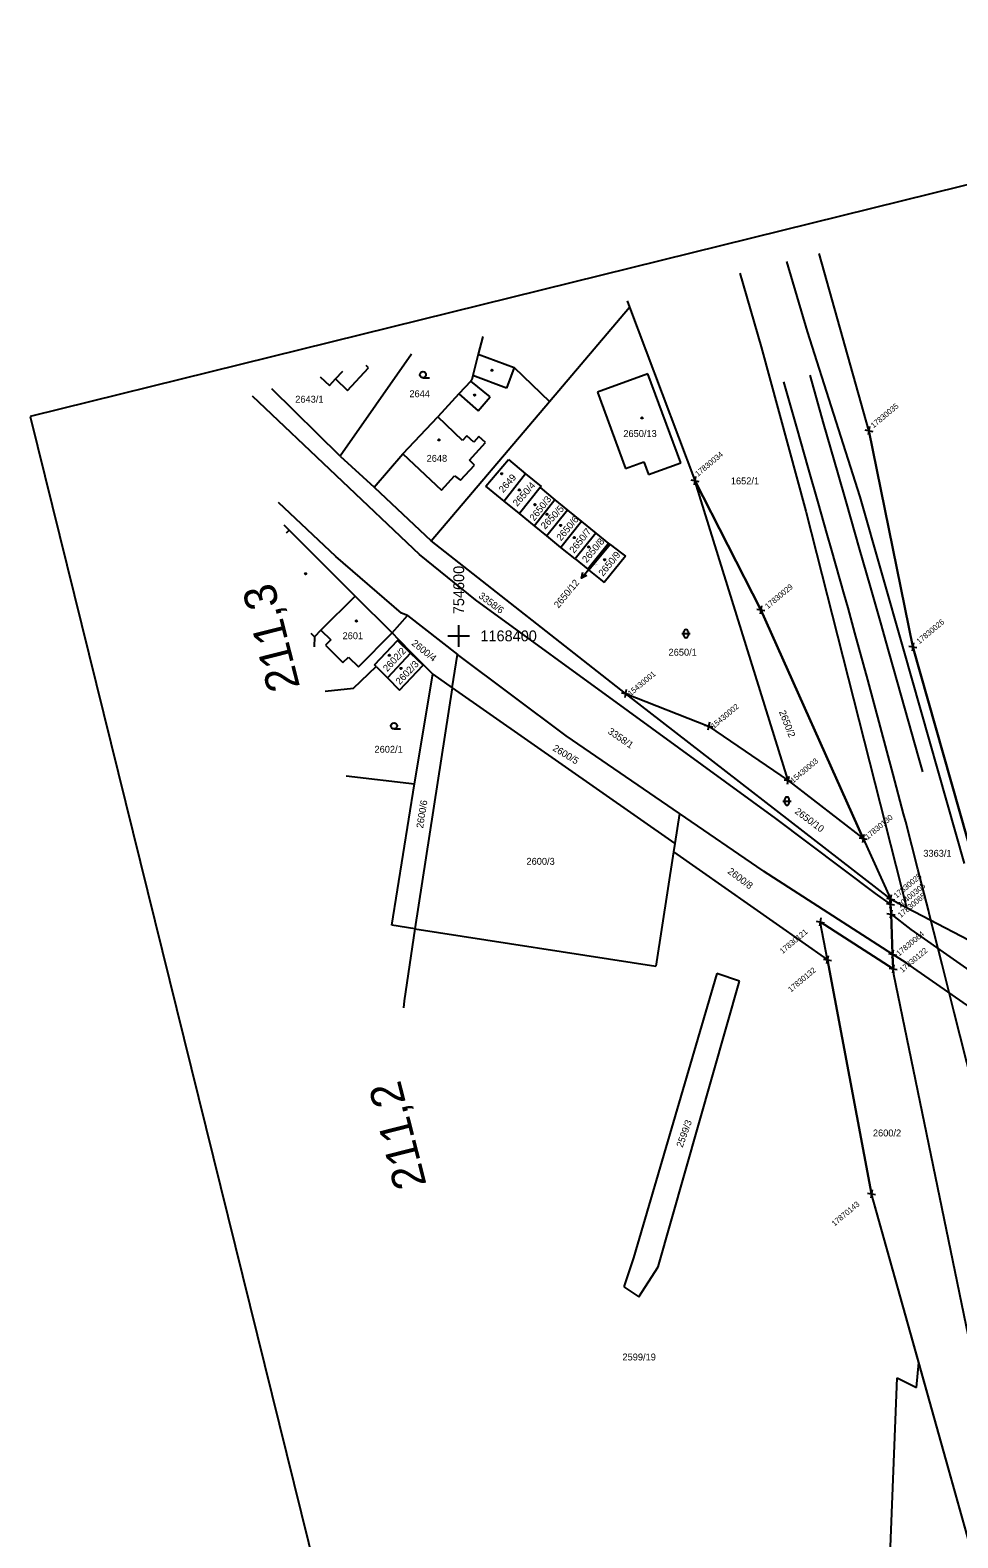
# Model space of a CAD drawing. Extents: x -754679 to -754173, y -1169241 to -1168288.
# Drawn here: x -754679.1 to -754507.9, y -1168566.4 to -1168288.2 of the extents above; entities that cross this region are included whole.
import ezdxf

# ---------------------------------------------------------------- set-up
doc = ezdxf.new("R2010")
doc.units = 0
for name, color, linetype in [('Default', 7, 'Continuous'), ('Vrstva 1', 7, 'Continuous'), ('Vrstva 16', 7, 'Continuous'), ('Vrstva 18', 7, 'Continuous'), ('Vrstva 19', 7, 'Continuous'), ('Vrstva 2', 7, 'Continuous'), ('Vrstva 25', 7, 'Continuous'), ('Vrstva 4', 7, 'Continuous'), ('Vrstva 52', 7, 'Continuous'), ('Vrstva 53', 7, 'Continuous'), ('Vrstva 6', 7, 'Continuous'), ('Vrstva 60', 7, 'Continuous'), ('Vrstva 61', 7, 'Continuous'), ('Vrstva 7', 7, 'Continuous')]:
    doc.layers.add(name, color=color, linetype=linetype)

msp = doc.modelspace()

# ---------------------------------------------------------------- linework, layer by layer
at = {"layer": 'Default'}
for points in [[(-754602, -1168400), (-754600, -1168400), (-754598, -1168400)], [(-754600, -1168402), (-754600, -1168400), (-754600, -1168398)]]:
    msp.add_lwpolyline(points, dxfattribs=at)
at = {"layer": 'Vrstva 1'}
for p, q in [((-754524.35, -1168362.13), (-754533.5, -1168329.43)), ((-754548.13, -1168333.05), (-754544.18, -1168346.64)), ((-754535.66, -1168343.83), (-754539.44, -1168330.9)), ((-754568.93, -1168338.2), (-754568.48, -1168339.37)), ((-754583.23, -1168356.74), (-754568.48, -1168339.37)), ((-754568.48, -1168339.37), (-754556.45, -1168371.36)), ((-754525.96, -1168374.32), (-754535.66, -1168343.83)), ((-754595.57, -1168344.78), (-754596.39, -1168348.05)), ((-754544.18, -1168346.64), (-754535.97, -1168376.96)), ((-754608.7, -1168348.03), (-754621.9, -1168366.83)), ((-754596.39, -1168348.05), (-754597.37, -1168351.97)), ((-754596.39, -1168348.05), (-754589.79, -1168350.49)), ((-754625.59, -1168352.21), (-754623.86, -1168353.81)), ((-754623.86, -1168353.81), (-754622.71, -1168352.59)), ((-754622.71, -1168352.59), (-754621.37, -1168351.16)), ((-754597.37, -1168351.97), (-754597.58, -1168352.78)), ((-754589.79, -1168350.49), (-754583.23, -1168356.74)), ((-754565.11, -1168351.62), (-754574.42, -1168355.03)), ((-754559.05, -1168368.08), (-754565.11, -1168351.62)), ((-754621.9, -1168366.83), (-754634.46, -1168354.4)), ((-754599.96, -1168355.34), (-754603.88, -1168359.61)), ((-754597.77, -1168353), (-754599.96, -1168355.34)), ((-754597.58, -1168352.78), (-754597.77, -1168353)), ((-754574.42, -1168355.03), (-754569.24, -1168369.1)), ((-754638.09, -1168355.74), (-754607.22, -1168384.99)), ((-754605.07, -1168382.45), (-754583.23, -1168356.74)), ((-754610.29, -1168366.43), (-754603.88, -1168359.61)), ((-754516.22, -1168402.04), (-754524.35, -1168362.13)), ((-754615.63, -1168372.59), (-754610.29, -1168366.43)), ((-754621.9, -1168366.83), (-754615.63, -1168372.59)), ((-754594.98, -1168372.37), (-754590.84, -1168367.46)), ((-754590.84, -1168367.46), (-754587.65, -1168370.08)), ((-754569.24, -1168369.1), (-754565.87, -1168367.86)), ((-754565.87, -1168367.86), (-754564.99, -1168370.22)), ((-754564.99, -1168370.22), (-754559.05, -1168368.08)), ((-754587.65, -1168370.08), (-754591.61, -1168375.13)), ((-754587.65, -1168370.08), (-754584.81, -1168372.41)), ((-754556.45, -1168371.36), (-754544.26, -1168395.2)), ((-754539.25, -1168426.67), (-754556.45, -1168371.36)), ((-754615.63, -1168372.59), (-754605.07, -1168382.45)), ((-754591.61, -1168375.13), (-754594.98, -1168372.37)), ((-754585, -1168372.64), (-754588.78, -1168377.44)), ((-754582.27, -1168374.88), (-754586.03, -1168379.68)), ((-754584.81, -1168372.41), (-754585, -1168372.64)), ((-754585, -1168372.64), (-754582.27, -1168374.88)), ((-754582.27, -1168374.88), (-754579.95, -1168376.79)), ((-754517.96, -1168402.36), (-754525.96, -1168374.32)), ((-754622.68, -1168385.36), (-754633.24, -1168375.36)), ((-754588.78, -1168377.44), (-754591.61, -1168375.13)), ((-754586.03, -1168379.68), (-754588.78, -1168377.44)), ((-754579.95, -1168376.79), (-754583.73, -1168381.56)), ((-754579.95, -1168376.79), (-754577.36, -1168378.91)), ((-754535.97, -1168376.96), (-754517.36, -1168450.11)), ((-754631.27, -1168380.5), (-754632.2, -1168379.57)), ((-754631.27, -1168380.5), (-754631.83, -1168381.07)), ((-754619.13, -1168392.66), (-754631.27, -1168380.5)), ((-754583.73, -1168381.56), (-754586.03, -1168379.68)), ((-754577.36, -1168378.91), (-754581.15, -1168383.67)), ((-754577.36, -1168378.91), (-754574.73, -1168381.07)), ((-754569.24, -1168410.61), (-754605.07, -1168382.45)), ((-754581.15, -1168383.67), (-754583.73, -1168381.56)), ((-754574.73, -1168381.07), (-754578.54, -1168385.8)), ((-754572.35, -1168382.93), (-754576.2, -1168387.69)), ((-754572.09, -1168383.13), (-754575.98, -1168387.89)), ((-754574.73, -1168381.07), (-754572.35, -1168382.93)), ((-754572.35, -1168382.93), (-754572.09, -1168383.13)), ((-754572.09, -1168383.13), (-754569.96, -1168384.76)), ((-754610.56, -1168395.83), (-754622.68, -1168385.36)), ((-754596.9, -1168393.33), (-754607.22, -1168384.99)), ((-754578.54, -1168385.8), (-754581.15, -1168383.67)), ((-754578.54, -1168385.8), (-754576.2, -1168387.69)), ((-754569.23, -1168385.32), (-754573.19, -1168390.17)), ((-754569.96, -1168384.76), (-754569.23, -1168385.32)), ((-754576.2, -1168387.69), (-754575.98, -1168387.89)), ((-754575.98, -1168387.89), (-754573.86, -1168389.59)), ((-754573.86, -1168389.59), (-754573.19, -1168390.17)), ((-754619.13, -1168392.66), (-754625.41, -1168398.93)), ((-754612.25, -1168399.44), (-754619.13, -1168392.66)), ((-754568.69, -1168413.91), (-754596.9, -1168393.33)), ((-754612.25, -1168399.44), (-754609.47, -1168396.21)), ((-754609.47, -1168396.21), (-754610.56, -1168395.83)), ((-754609.47, -1168396.21), (-754600.23, -1168403.42)), ((-754544.26, -1168395.2), (-754525.37, -1168437.38)), ((-754625.41, -1168398.93), (-754626.63, -1168400.15)), ((-754612.25, -1168399.44), (-754611.1, -1168400.65)), ((-754626.63, -1168400.15), (-754626.65, -1168402.02)), ((-754615.54, -1168405.32), (-754611.31, -1168400.87)), ((-754611.31, -1168400.87), (-754611.1, -1168400.65)), ((-754611.1, -1168400.65), (-754608.75, -1168403.04)), ((-754506.68, -1168442.02), (-754517.96, -1168402.36)), ((-754501.97, -1168452.25), (-754516.22, -1168402.04)), ((-754615.2, -1168405.67), (-754615.54, -1168405.32)), ((-754608.88, -1168403.18), (-754613.16, -1168407.73)), ((-754610.9, -1168410.02), (-754606.53, -1168405.42)), ((-754608.75, -1168403.04), (-754608.88, -1168403.18)), ((-754608.75, -1168403.04), (-754606.47, -1168405.36)), ((-754606.53, -1168405.42), (-754606.47, -1168405.36)), ((-754606.47, -1168405.36), (-754604.79, -1168407.06)), ((-754601.19, -1168409.58), (-754600.23, -1168403.42)), ((-754580.15, -1168418.44), (-754600.23, -1168403.42)), ((-754619.41, -1168409.65), (-754615.2, -1168405.67)), ((-754615.2, -1168405.67), (-754613.16, -1168407.73)), ((-754613.16, -1168407.73), (-754610.9, -1168410.02)), ((-754608.13, -1168427.31), (-754604.79, -1168407.06)), ((-754604.79, -1168407.06), (-754601.19, -1168409.58)), ((-754624.62, -1168410.22), (-754619.41, -1168409.65)), ((-754601.19, -1168409.58), (-754608.11, -1168454.05)), ((-754601.19, -1168409.58), (-754560.12, -1168438.32)), ((-754520.37, -1168448.54), (-754569.24, -1168410.61)), ((-754569.24, -1168410.61), (-754553.89, -1168416.63)), ((-754541.48, -1168433.71), (-754568.69, -1168413.91)), ((-754553.89, -1168416.63), (-754539.25, -1168426.67)), ((-754559.26, -1168432.78), (-754580.15, -1168418.44)), ((-754514.38, -1168425.11), (-754515.12, -1168422.49)), ((-754620.77, -1168425.8), (-754608.13, -1168427.31)), ((-754612.34, -1168453.39), (-754608.13, -1168427.31)), ((-754539.25, -1168426.67), (-754525.37, -1168437.38)), ((-754559.26, -1168432.78), (-754560.12, -1168438.32)), ((-754543.86, -1168443.35), (-754559.26, -1168432.78)), ((-754523.09, -1168447.51), (-754541.48, -1168433.71)), ((-754560.12, -1168438.32), (-754560.36, -1168439.85)), ((-754525.37, -1168437.38), (-754520.37, -1168448.54)), ((-754560.36, -1168439.85), (-754563.64, -1168460.96)), ((-754543.86, -1168443.35), (-754519.95, -1168458.75)), ((-754520.33, -1168449.52), (-754523.09, -1168447.51)), ((-754520.37, -1168448.54), (-754517.36, -1168450.11)), ((-754520.37, -1168448.54), (-754520.33, -1168449.52)), ((-754520.33, -1168449.52), (-754520.25, -1168451.35)), ((-754517.36, -1168450.11), (-754497.45, -1168460.53)), ((-754519.84, -1168461.42), (-754533.3, -1168452.78)), ((-754531.99, -1168459.75), (-754533.3, -1168452.78)), ((-754520.25, -1168451.35), (-754519.95, -1168458.75)), ((-754513.14, -1168451.47), (-754513.35, -1168450.62)), ((-754608.11, -1168454.05), (-754612.34, -1168453.39)), ((-754608.11, -1168454.05), (-754563.64, -1168460.96)), ((-754531.99, -1168459.75), (-754523.85, -1168502.96)), ((-754519.95, -1168458.75), (-754519.84, -1168461.42)), ((-754552.4, -1168462.3), (-754567.78, -1168514.73)), ((-754563.21, -1168516.41), (-754548.2, -1168463.7)), ((-754548.2, -1168463.7), (-754552.4, -1168462.3)), ((-754519.84, -1168461.42), (-754519.8, -1168462.41)), ((-754519.8, -1168462.41), (-754486.32, -1168624.94)), ((-754515.13, -1168534.05), (-754523.85, -1168502.96)), ((-754567.78, -1168514.73), (-754569.52, -1168520.08)), ((-754566.76, -1168521.95), (-754563.21, -1168516.41)), ((-754569.52, -1168520.08), (-754566.76, -1168521.95)), ((-754502.42, -1168579.34), (-754515.13, -1168534.05))]:
    msp.add_line(p, q, dxfattribs=at)
for points in [[(-754515.12, -1168422.49), (-754517.72, -1168413.32), (-754521.2, -1168400.93), (-754522.02, -1168398.05), (-754524.11, -1168390.71), (-754525.99, -1168384.14), (-754528.54, -1168375.21), (-754530.06, -1168369.88), (-754532.62, -1168360.91), (-754535.19, -1168351.89)], [(-754532.08, -1168381.05), (-754533.64, -1168375.56), (-754535.53, -1168368.95), (-754537.58, -1168361.76), (-754540.04, -1168353.12)], [(-754513.35, -1168450.62), (-754515.29, -1168443.04), (-754517.54, -1168434.32), (-754517.92, -1168432.84), (-754519.83, -1168425.59), (-754522.16, -1168416.85), (-754524.53, -1168408.11), (-754526.91, -1168399.43), (-754528.18, -1168394.85), (-754528.89, -1168392.32), (-754531.16, -1168384.27), (-754532.08, -1168381.05)], [(-754498.39, -1168509.75), (-754500.09, -1168503), (-754500.37, -1168501.89), (-754500.59, -1168501.05), (-754502.8, -1168492.33), (-754502.98, -1168491.62), (-754505.01, -1168483.59), (-754507.47, -1168473.86), (-754508.58, -1168469.47), (-754510.81, -1168460.63), (-754513.14, -1168451.47)]]:
    msp.add_lwpolyline(points, dxfattribs=at)
at = {"layer": 'Vrstva 16'}
msp.add_line((-754577.37, -1168389.32), (-754575.44, -1168387.02), dxfattribs=at)
msp.add_lwpolyline([(-754576.34, -1168388.87), (-754577.37, -1168389.32), (-754577.11, -1168388.23)], dxfattribs=at)
at = {"layer": 'Vrstva 25'}
for p, q in [((-754606.6, -1168352.37), (-754605.4, -1168352.37)), ((-754558.83, -1168399.58), (-754557.33, -1168399.58)), ((-754558.45, -1168399.96), (-754558.45, -1168399.21)), ((-754557.7, -1168399.21), (-754557.7, -1168399.96)), ((-754611.94, -1168417.16), (-754610.74, -1168417.16)), ((-754540.19, -1168430.49), (-754538.69, -1168430.49)), ((-754539.82, -1168430.86), (-754539.82, -1168430.11)), ((-754539.07, -1168430.11), (-754539.07, -1168430.86))]:
    msp.add_line(p, q, dxfattribs=at)
for centre, radius in [((-754606.6, -1168351.81), 0.562), ((-754593.87, -1168350.99), 0.131), ((-754597.08, -1168355.58), 0.131), ((-754566.18, -1168359.77), 0.131), ((-754603.66, -1168363.85), 0.131), ((-754592.06, -1168370.1), 0.131), ((-754588.82, -1168373.06), 0.131), ((-754585.95, -1168375.79), 0.131), ((-754583.72, -1168377.55), 0.131), ((-754581.22, -1168379.63), 0.131), ((-754578.7, -1168381.86), 0.131), ((-754576.01, -1168383.58), 0.131), ((-754574.25, -1168385.53), 0.131), ((-754573.08, -1168385.96), 0.131), ((-754628.25, -1168388.54), 0.131), ((-754618.86, -1168397.25), 0.131), ((-754612.8, -1168403.56), 0.131), ((-754610.65, -1168406.01), 0.131), ((-754611.94, -1168416.6), 0.562)]:
    msp.add_circle(centre, radius, dxfattribs=at)
for centre, start, end in [((-754558.08, -1168399.21), 0, 180), ((-754558.08, -1168399.96), 180, 0), ((-754539.44, -1168430.11), 0, 180), ((-754539.44, -1168430.86), 180, 0)]:
    msp.add_arc(centre, 0.375, start, end, dxfattribs=at)
at = {"layer": 'Vrstva 4'}
for p, q in [((-754622.71, -1168352.59), (-754620.5, -1168354.7)), ((-754620.5, -1168354.7), (-754616.62, -1168350.55)), ((-754616.62, -1168350.55), (-754617.09, -1168350.11)), ((-754591.17, -1168354.27), (-754597.37, -1168351.97)), ((-754589.79, -1168350.49), (-754591.17, -1168354.27)), ((-754599.96, -1168355.34), (-754596.39, -1168358.48)), ((-754594.17, -1168355.89), (-754597.77, -1168353)), ((-754596.39, -1168358.48), (-754594.17, -1168355.89)), ((-754599.28, -1168363.92), (-754603.88, -1168359.61)), ((-754598.51, -1168363.1), (-754599.28, -1168363.92)), ((-754597.22, -1168364.26), (-754598.51, -1168363.1)), ((-754596.29, -1168363.23), (-754597.22, -1168364.26)), ((-754595.06, -1168364.32), (-754596.29, -1168363.23)), ((-754610.29, -1168366.43), (-754603.16, -1168373.1)), ((-754598.04, -1168367.6), (-754595.06, -1168364.32)), ((-754599.68, -1168371.28), (-754597.08, -1168368.53)), ((-754597.08, -1168368.53), (-754598.04, -1168367.6)), ((-754603.16, -1168373.1), (-754600.77, -1168370.5)), ((-754600.77, -1168370.5), (-754599.68, -1168371.28)), ((-754627.27, -1168399.51), (-754626.63, -1168400.15)), ((-754625.41, -1168398.93), (-754623.61, -1168400.7)), ((-754618.51, -1168405.72), (-754612.25, -1168399.44)), ((-754623.61, -1168400.7), (-754624.6, -1168401.69)), ((-754624.6, -1168401.69), (-754621.36, -1168404.94)), ((-754611.31, -1168400.87), (-754608.88, -1168403.18)), ((-754621.36, -1168404.94), (-754620.32, -1168403.91)), ((-754620.32, -1168403.91), (-754618.51, -1168405.72)), ((-754608.88, -1168403.18), (-754606.53, -1168405.42)), ((-754520.25, -1168451.35), (-754516.61, -1168454.2)), ((-754516.61, -1168454.2), (-754501.51, -1168464.78)), ((-754517.48, -1168460.34), (-754519.95, -1168458.75)), ((-754502.71, -1168470.6), (-754517.48, -1168460.34))]:
    msp.add_line(p, q, dxfattribs=at)
at = {"layer": 'Vrstva 53'}
for p, q in [((-754524.35, -1168362.13), (-754516.22, -1168402.04)), ((-754544.26, -1168395.2), (-754556.45, -1168371.36)), ((-754525.37, -1168437.38), (-754544.26, -1168395.2)), ((-754516.22, -1168402.04), (-754501.97, -1168452.25)), ((-754520.37, -1168448.54), (-754569.24, -1168410.61)), ((-754569.24, -1168410.61), (-754553.89, -1168416.63)), ((-754553.89, -1168416.63), (-754539.25, -1168426.67)), ((-754539.25, -1168426.67), (-754525.37, -1168437.38)), ((-754520.33, -1168449.52), (-754520.37, -1168448.54)), ((-754520.25, -1168451.35), (-754520.33, -1168449.52)), ((-754531.99, -1168459.75), (-754533.3, -1168452.78)), ((-754533.3, -1168452.78), (-754519.84, -1168461.42)), ((-754519.95, -1168458.75), (-754520.25, -1168451.35)), ((-754523.85, -1168502.96), (-754531.99, -1168459.75)), ((-754519.84, -1168461.42), (-754519.95, -1168458.75)), ((-754490.14, -1168623.07), (-754523.85, -1168502.96))]:
    msp.add_line(p, q, dxfattribs=at)
at = {"layer": 'Vrstva 6'}
for p, q in [((-754560.36, -1168439.85), (-754531.99, -1168459.75)), ((-754608.11, -1168454.05), (-754610.08, -1168467.32)), ((-754610.08, -1168467.32), (-754610.18, -1168468.62)), ((-754515.57, -1168538.69), (-754515.13, -1168534.05)), ((-754521.52, -1168598.96), (-754519.11, -1168536.88)), ((-754519.11, -1168536.88), (-754515.57, -1168538.69))]:
    msp.add_line(p, q, dxfattribs=at)
at = {"layer": 'Vrstva 60'}
for p, q in [((-754525.09, -1168362), (-754523.61, -1168362.26)), ((-754524.22, -1168361.39), (-754524.48, -1168362.87)), ((-754557.19, -1168371.23), (-754555.71, -1168371.49)), ((-754556.32, -1168370.62), (-754556.58, -1168372.1)), ((-754544.13, -1168394.46), (-754544.39, -1168395.94)), ((-754545, -1168395.07), (-754543.52, -1168395.33)), ((-754516.96, -1168401.91), (-754515.48, -1168402.17)), ((-754516.09, -1168401.3), (-754516.35, -1168402.78)), ((-754569.98, -1168410.48), (-754568.5, -1168410.74)), ((-754569.11, -1168409.87), (-754569.37, -1168411.35)), ((-754554.63, -1168416.5), (-754553.15, -1168416.76)), ((-754553.76, -1168415.89), (-754554.02, -1168417.37)), ((-754539.99, -1168426.54), (-754538.51, -1168426.8)), ((-754539.12, -1168425.93), (-754539.38, -1168427.41)), ((-754526.11, -1168437.25), (-754524.63, -1168437.51)), ((-754525.24, -1168436.64), (-754525.5, -1168438.12)), ((-754521.11, -1168448.41), (-754519.63, -1168448.67)), ((-754521.07, -1168449.39), (-754519.59, -1168449.65)), ((-754520.24, -1168447.8), (-754520.5, -1168449.28)), ((-754520.2, -1168448.78), (-754520.46, -1168450.26)), ((-754534.04, -1168452.65), (-754532.56, -1168452.91)), ((-754533.17, -1168452.04), (-754533.43, -1168453.52)), ((-754520.99, -1168451.22), (-754519.51, -1168451.48)), ((-754520.12, -1168450.61), (-754520.38, -1168452.09)), ((-754519.82, -1168458.01), (-754520.08, -1168459.49)), ((-754532.73, -1168459.62), (-754531.25, -1168459.88)), ((-754531.86, -1168459.01), (-754532.12, -1168460.49)), ((-754520.69, -1168458.62), (-754519.21, -1168458.88)), ((-754519.71, -1168460.68), (-754519.97, -1168462.16)), ((-754520.58, -1168461.29), (-754519.1, -1168461.55)), ((-754524.59, -1168502.83), (-754523.11, -1168503.09)), ((-754523.72, -1168502.22), (-754523.98, -1168503.7))]:
    msp.add_line(p, q, dxfattribs=at)
at = {"layer": 'Vrstva 61'}
msp.add_line((-754679.07, -1168359.54), (-754578.24, -1168767.26), dxfattribs=at)
msp.add_lwpolyline([(-754578.24, -1168767.26), (-754289.93, -1168695.96), (-754390.75, -1168288.24), (-754679.07, -1168359.54)], dxfattribs=at)

# ---------------------------------------------------------------- texts
at = {"layer": 'Default'}
msp.add_text('754600', height=2, rotation=90, dxfattribs=at).set_placement((-754599, -1168396))
msp.add_text('1168400', height=2, dxfattribs=at).set_placement((-754596, -1168401))
at = {"layer": 'Vrstva 16'}
msp.add_text('2650/12', height=1.275, rotation=50.4203, dxfattribs=at).set_placement((-754581.59, -1168394.99))
at = {"layer": 'Vrstva 18'}
for s, rotation, p in [('2644', 360, (-754609.1, -1168355.96)), ('2643/1', 360, (-754630.16, -1168356.97)), ('1652/1', 360, (-754549.8, -1168372.05)), ('3358/6', 323.0909, (-754596.44, -1168392.86)), ('2600/4', 321.3147, (-754608.81, -1168401.57)), ('2650/1', 360, (-754561.29, -1168403.65)), ('2650/2', 291.5782, (-754540.94, -1168414.02)), ('3358/1', 325.5322, (-754572.61, -1168417.9)), ('2602/1', 360, (-754615.54, -1168421.56)), ('2600/5', 328.4767, (-754582.79, -1168421.04)), ('2600/6', 81.0162, (-754606.58, -1168435.56)), ('2650/10', 323.0909, (-754538.12, -1168432.62)), ('2600/3', 360, (-754587.5, -1168442.23)), ('3363/1', 360, (-754514.29, -1168440.75)), ('2600/8', 323.0909, (-754550.51, -1168443.68)), ('2599/3', 70.1873, (-754558.71, -1168494.49)), ('2600/2', 360, (-754523.59, -1168492.35)), ('2599/19', 360, (-754569.79, -1168533.68))]:
    msp.add_text(s, height=1.275, rotation=rotation, dxfattribs=at).set_placement(p)
at = {"layer": 'Vrstva 19'}
for s, rotation, p in [('2650/13', 360, (-754569.63, -1168363.31)), ('2648', 360, (-754605.93, -1168367.88)), ('2649', 48.5868, (-754591.79, -1168373.68)), ('2650/4', 48.4149, (-754589.21, -1168376.21)), ('2650/3', 51.6808, (-754586.06, -1168378.9)), ('2650/5', 46.1804, (-754584.08, -1168380.42)), ('2650/6', 50.0765, (-754581.12, -1168382.56)), ('2650/7', 51.5662, (-754578.71, -1168384.85)), ('2650/8', 49.6754, (-754576.4, -1168386.61)), ('2650/9', 50.7068, (-754573.37, -1168389.1)), ('2601', 360, (-754621.43, -1168400.61)), ('2602/2', 46.9825, (-754613.18, -1168406.69)), ('2602/3', 46.6388, (-754610.85, -1168409.09))]:
    msp.add_text(s, height=1.275, rotation=rotation, dxfattribs=at).set_placement(p)
msp.add_text('2650/12', height=0.2, dxfattribs=at).set_placement((-754575.4, -1168387.01))
at = {"layer": 'Vrstva 2'}
for s, p in [(' 17830035', (-754523.76, -1168361.98)), (' 17830034', (-754556.15, -1168370.91)), (' 17830029', (-754543.26, -1168395.33)), (' 17830026', (-754515.32, -1168401.82))]:
    msp.add_text(s, height=1.037, rotation=40, dxfattribs=at).set_placement(p)
at = {"layer": 'Vrstva 52'}
for s, p in [(' 15430001', (-754568.57, -1168411.4)), (' 15430002', (-754553.22, -1168417.42)), (' 15430003', (-754538.58, -1168427.46)), (' 17830130', (-754524.83, -1168437.87)), (' 17830025', (-754519.52, -1168448.71)), (' 20400305', (-754518.83, -1168450.48)), (' 17830065', (-754518.75, -1168452.31)), (' 17830121', (-754540.54, -1168458.97)), (' 17830064', (-754519.04, -1168459.38)), (' 17830122', (-754518.43, -1168462.44)), (' 17830132', (-754539.01, -1168466.06)), (' 17870143', (-754530.97, -1168509.23))]:
    msp.add_text(s, height=1.037, rotation=40, dxfattribs=at).set_placement(p)
at = {"layer": 'Vrstva 7'}
for s, p in [('211,3', (-754629.25, -1168409.4)), ('211,2', (-754605.91, -1168501.23))]:
    msp.add_text(s, height=6, rotation=104.1773, dxfattribs=at).set_placement(p)

doc.saveas('drawing.dxf')
